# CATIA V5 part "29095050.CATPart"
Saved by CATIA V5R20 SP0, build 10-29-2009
Part number: 29095050
Definition: NONE
Nomenclature: 29095050
Source: Unknown
Description: 29095050
Bounding box of the stored display mesh (mm): x -25 to 44.548, y -61.5 to 96.048, z -51.5 to 51.5
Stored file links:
  C:\Users\Utente\Desktop\IO LAVORO\3D X SITO CF\X SITO\PLASTICA\RF1\29095050.CATPart
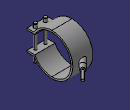
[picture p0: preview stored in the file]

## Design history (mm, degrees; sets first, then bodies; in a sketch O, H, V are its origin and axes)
Body1 "29095050" (main body)
  Solid1: solid without history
